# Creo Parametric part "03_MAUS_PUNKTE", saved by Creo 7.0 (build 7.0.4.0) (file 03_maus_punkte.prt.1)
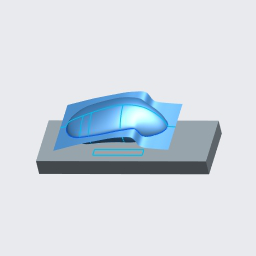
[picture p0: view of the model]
Units: millimeter Kilogram Sec (mmKs); MM, KILOGRAM, SECS

Created from: MAUS_MASTER_NEU.PRT

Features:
  1. datum plane "RIGHT"
  2. datum plane "TOP"
  3. datum plane "FRONT"
  4. coordinate system
  5. curve
  6. curve
  7. datum plane "DTM1"
  8. curve
  9. curve
  10. curve
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
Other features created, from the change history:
  datum plane "DTM2"
  datum point "PNT17" (2 times)
  pattern "Muster 1"
  datum point "PNT18"
  datum point "PNT19"
  datum point "PNT20"
  datum point "PNT21"
  datum point "PNT22"
  datum point "PNT23"
  datum point "PNT24"
  datum point "PNT25"
  datum point "PNT26"
  datum point "PNT27"
  datum point "PNT28"
  datum point "PNT29"
  datum point "PNT30"
  datum point "PNT31"
  datum point "PNT32"
  datum point "PNT33"
  datum point "PNT34"
  datum point "PNT35"
  datum point "PNT36"
  datum point "PNT37"
  extrusion "Profil 2"
  curve "Kopieren 1"
  datum point "Bezugspunkt ID 1598"
  sketch "Skizze 8"
  datum point "Bezugspunkt ID 1609"

Other named items: TEIL2, TEIL3, TEIL1

Layers: 01_EBENEN, 01_KURVEN, 01_PUNKTE, 02_EBENEN, 02_KURVEN, 02_PUNKTE, ALLE, FLAECHEN, KURVENELEMENTE, SAMMELFLÄCHEN, VOLUMENGEOMETRIE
